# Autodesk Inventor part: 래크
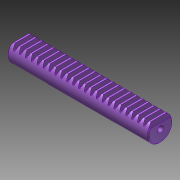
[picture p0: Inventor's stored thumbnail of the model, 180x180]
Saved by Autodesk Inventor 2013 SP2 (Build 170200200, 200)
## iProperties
Created: 2024-11
Part Number: 래크
Material: Generic
Document SubType Name: Modeling
Designer: a
Density: 1 g/cm^3
Author: a
변환 표준: STEP AP214IS
전처리기: Build: 200, Release: 2013 SP2 Update 6 - Date: Thu 07/17/2014
전송 단위: 밀리미터
불확실성: 0.01
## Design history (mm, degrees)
node "래크1"
node "솔리드1"
node "기준1"
